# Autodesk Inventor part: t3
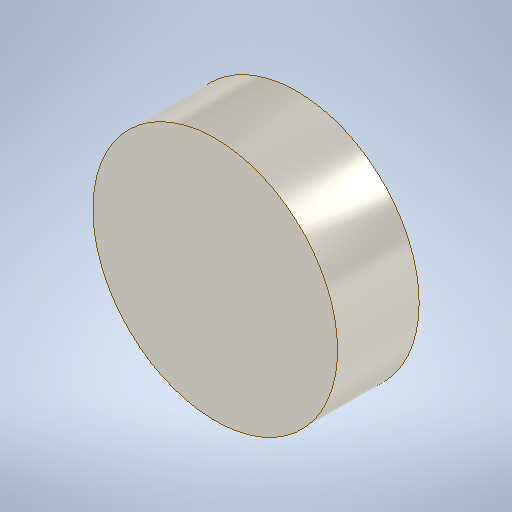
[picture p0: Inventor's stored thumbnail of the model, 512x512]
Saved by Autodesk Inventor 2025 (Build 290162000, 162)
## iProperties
Created: 2025-01
Part Number: t3
Material: Titanium
Document SubType Name: Modeling
Designer: dansp
Mass: 3.98491 g
Surface Area: 5.89049 cm^2
Volume: 0.883573 cm^3
Density: 4.51 g/cm^3
Appearance: Titanium
Author: dansp
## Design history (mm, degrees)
sketch "Sketch1"
  geometry: L1 (0, 10.5)-(0, -10.5) reference; L2 (-10.5, 0)-(10.5, 0) reference; C1 r 7.5 at (0, 0); 1 further point
  constraints: 1 centre point, 1 coincident
  dimensions: "d0" = 15 diameter of C1
extrude "Extrusion1" new body sketch "Sketch1" distance "d1" = 5; taper "d2" = 0 deg
body "Solid1"
